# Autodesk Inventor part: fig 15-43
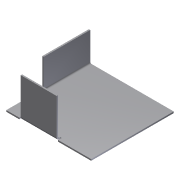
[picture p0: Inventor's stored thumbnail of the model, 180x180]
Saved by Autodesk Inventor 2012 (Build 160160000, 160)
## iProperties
Created: 2005-03
Part Number: fig 15-43
Document SubType Name: Sheet Metal
Designer: CADCIM
Manufacturer: Standard
Standards Organization: Custom
Density: 1 g/cm^3
Sheet Metal Rule: Default
Material: Default
Author: CADCIM
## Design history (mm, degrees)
node "Face1"
  sketch "Sketch1"
    geometry: L1 (-29, -26)-(30, -26); L2 (30, -26)-(30, 31.375); L3 (30, 31.375)-(-29, 31.375); L4 (-29, 31.375)-(-29, -26)
    constraints: 8 end point, 2 parallel, 1 horizontal, 1 perpendicular
node "Flange1"
node "Flange2"
body "Solid1"
face "Plate1" dims "Thickness" = 1
sketch "Sketch2"
  geometry: L1 (25, 0)-(57.375, 0); L2 (57.375, 0)-(57.375, 20); L3 (57.375, 20)-(25, 20); L4 (25, 20)-(25, 0)
  constraints: 8 end point
face "Plate2" dims "d1" = 0, "d2" = 25, "d3" = 1 (= BendReliefWidth), "d5" = 2 (= MinimumRemnant), "d7" = 20, "d8" = 90 deg, "d9" = 1 (= BendRadius), "Thickness" = 1
bend "Bend1" dims "d3" = 1 (= BendReliefWidth), "d4" = 0.5 (= BendReliefDepth), "d5" = 2 (= MinimumRemnant), "d6" = 1 (= BendRadius), "d7" = 20, "d8" = 90 deg, "d9" = 1 (= BendRadius), "SeamGap" = 0.01, "Thickness" = 1
sketch "Sketch3"
  geometry: L1 (49, 0)-(24, 0); L2 (24, 0)-(24, 26); L3 (24, 26)-(49, 26); L4 (49, 26)-(49, 0)
  constraints: 8 end point
face "Plate3" dims "d12" = 1 (= BendReliefWidth), "d14" = 2 (= MinimumRemnant), "d16" = 26, "d17" = 90 deg, "d18" = 1 (= BendRadius), "d19" = 10, "d20" = 25, "Thickness" = 1
bend "Bend2" dims "d12" = 1 (= BendReliefWidth), "d13" = 0.5 (= BendReliefDepth), "d14" = 2 (= MinimumRemnant), "d15" = 1 (= BendRadius), "d16" = 26, "d17" = 90 deg, "d18" = 1 (= BendRadius), "SeamGap" = 0.01, "Thickness" = 1
other parameters: "BendRadius" = 1 (= Thickness), "BendReliefWidth" = 1 (= Thickness), "BendReliefDepth" = 0.5 (= 0.5 x Thickness), "CornerReliefSize" = 4 (= 4 x Thickness), "MinimumRemnant" = 2 (= 2 x Thickness), "TransitionRadius" = 1 (= BendRadius), "d0" = 1 (= BendRadius), "JacobiRadiusSize" = 1 (= Thickness), "GapSize" = 1 (= Thickness)
